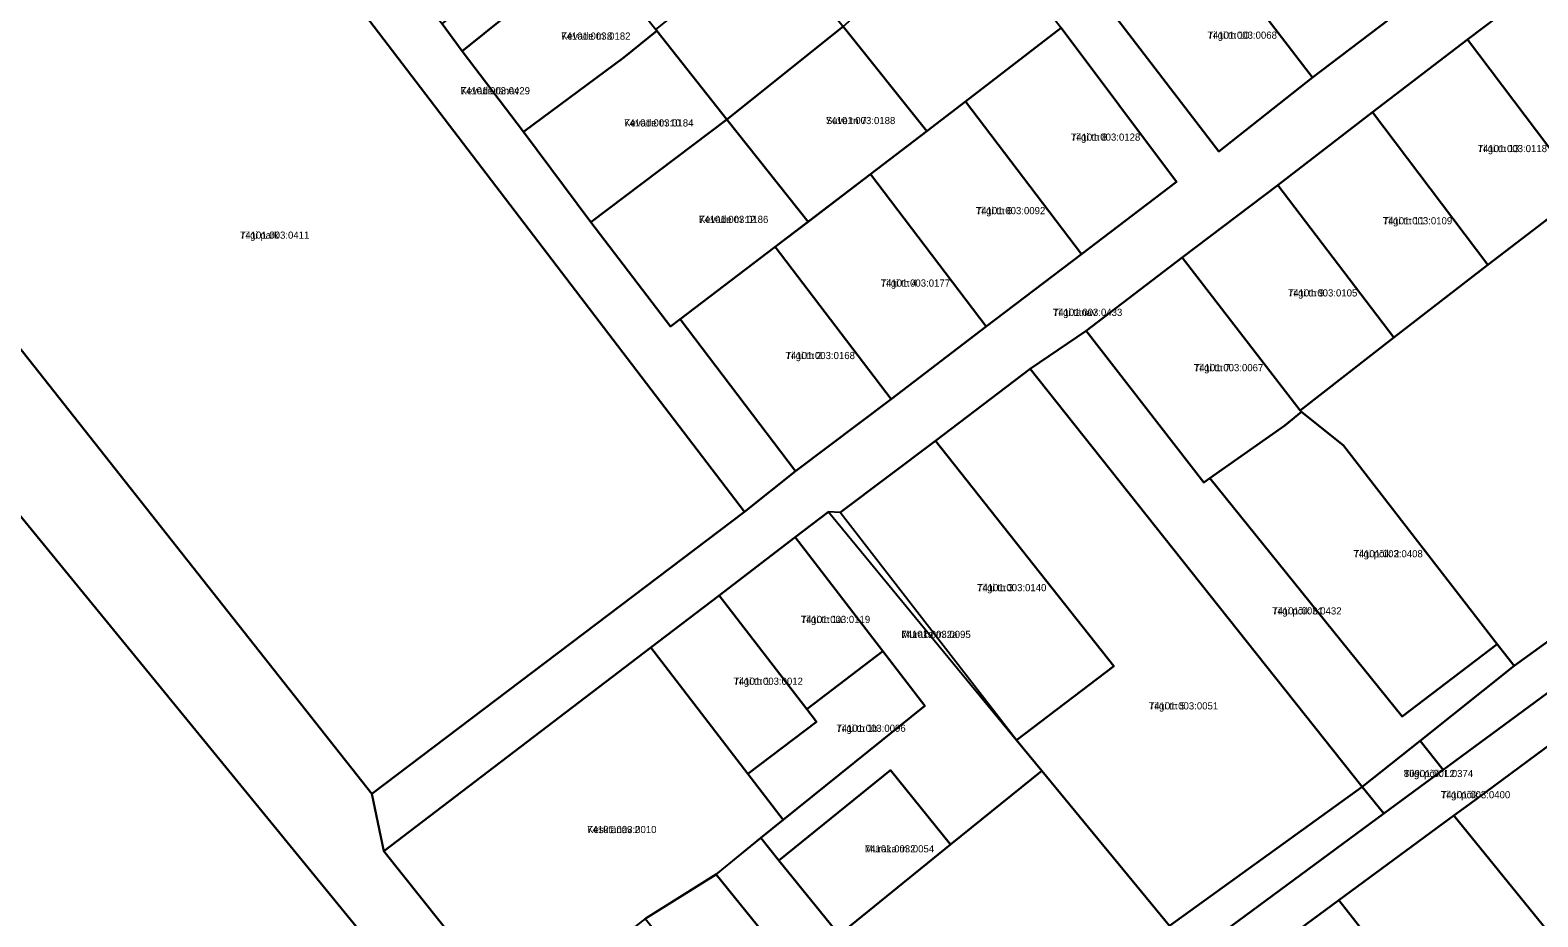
# Model space of a CAD drawing. Extents: x 524000 to 564260, y 6469338 to 6496391.
# Drawn here: x 538716.5 to 539031.7, y 6473655.1 to 6473840.4 of the extents above; entities that cross this region are included whole.
import ezdxf

# ---------------------------------------------------------------- set-up
doc = ezdxf.new("R2010")
doc.units = 0
for name, color, linetype in [('L_AADRESS', 7, 'Continuous'), ('PIIR', 7, 'Continuous'), ('TUNNUS', 7, 'Continuous')]:
    doc.layers.add(name, color=color, linetype=linetype)

msp = doc.modelspace()

# ---------------------------------------------------------------- linework, layer by layer
at = {"layer": 'PIIR'}
for points in [[(539001.2, 6473992.51), (538977.96, 6473973.83), (538953.19, 6473953.88), (538929.74, 6473935), (538905.62, 6473915.58), (538881.14, 6473895.86), (538857.67, 6473876.96), (538833.73, 6473857.7), (538806.82, 6473836.05), (538802.62, 6473841.76), (538829.42, 6473863.31), (538852.81, 6473882.12), (538877.13, 6473901.67), (538901.18, 6473920.98), (538925.27, 6473940.39), (538950.53, 6473960.69), (538973.46, 6473979.05), (538996.83, 6473997.86)], [(538746.69, 6473914.49), (538764.11, 6473892.45), (538777.15, 6473875.29), (538790.03, 6473858.33), (538802.62, 6473841.76), (538806.82, 6473836.05), (538819.61, 6473819.18), (538833.73, 6473800.28), (538850.34, 6473778.48), (538852.39, 6473780.04), (538876.52, 6473748.26), (538865.85, 6473739.73), (538736.45, 6473909.29)], [(538736.45, 6473909.29), (538865.85, 6473739.73), (538787.92, 6473680.82), (538654.87, 6473849.17)], [(538903.96, 6473819.33), (538886.44, 6473841.18), (538908.3, 6473860.63), (538934.93, 6473880.53), (538953.63, 6473857.22), (538945.95, 6473851.6), (538942.73, 6473855.45), (538928.99, 6473844.86), (538932.05, 6473840.9), (538912.03, 6473825.5)], [(538978.02, 6473875.71), (538980.21, 6473877.38), (539004.54, 6473845.63), (538984.63, 6473830.51), (538960.3, 6473862.25)], [(538960.3, 6473862.25), (538984.63, 6473830.51), (538964.98, 6473815.05), (538940.68, 6473846.82), (538945.95, 6473851.6), (538953.63, 6473857.22)], [(538847.31, 6473840.54), (538871.49, 6473859.78), (538886.44, 6473841.18), (538862.17, 6473821.77), (538847.5, 6473840.31)], [(538806.82, 6473836.05), (538833.73, 6473857.7), (538847.31, 6473840.54), (538847.5, 6473840.31), (538840.6, 6473834.68), (538819.61, 6473819.18)], [(539036.94, 6473853.58), (539061.24, 6473821.71), (539062.33, 6473820.29), (539053.46, 6473813.59), (539052.38, 6473815.03), (539041.12, 6473806.54), (539017.03, 6473838.47)], [(538819.61, 6473819.18), (538840.6, 6473834.68), (538847.5, 6473840.31), (538862.17, 6473821.77), (538833.73, 6473800.28)], [(538862.17, 6473821.77), (538886.44, 6473841.18), (538903.96, 6473819.33), (538892.17, 6473810.31), (538879.14, 6473800.39)], [(538912.03, 6473825.5), (538932.05, 6473840.9), (538956.15, 6473808.75), (538936.28, 6473793.58)], [(539061.24, 6473821.71), (539082.73, 6473838.08), (539088.7, 6473810.88), (539091.71, 6473754.61), (539026.77, 6473707.59), (539023.2, 6473712.09), (538991.08, 6473753.62), (538982.33, 6473760.65), (538982.02, 6473760.95), (539001.62, 6473776.19), (539021.24, 6473791.4), (539041.12, 6473806.54), (539052.38, 6473815.03), (539053.46, 6473813.59), (539062.33, 6473820.29)], [(539017.03, 6473838.47), (539041.12, 6473806.54), (539021.24, 6473791.4), (538997.15, 6473823.31)], [(538892.17, 6473810.31), (538903.96, 6473819.33), (538912.03, 6473825.5), (538936.28, 6473793.58), (538916.37, 6473778.46)], [(538833.73, 6473800.28), (538862.17, 6473821.77), (538879.14, 6473800.39), (538872.28, 6473795.17), (538852.39, 6473780.04), (538850.34, 6473778.48)], [(538997.15, 6473823.31), (539021.24, 6473791.4), (539001.62, 6473776.19), (538977.38, 6473808.01)], [(538892.17, 6473810.31), (538916.37, 6473778.46), (538896.48, 6473763.32), (538872.28, 6473795.17)], [(538977.38, 6473808.01), (539001.62, 6473776.19), (538982.02, 6473760.95), (538957.32, 6473792.91)], [(538872.28, 6473795.17), (538896.48, 6473763.32), (538876.52, 6473748.26), (538852.39, 6473780.04)], [(538937.29, 6473777.59), (538957.32, 6473792.91), (538982.02, 6473760.95), (538982.33, 6473760.65), (538978.84, 6473757.8), (538963.11, 6473746.78), (538961.91, 6473745.87)], [(538937.29, 6473777.59), (538961.91, 6473745.87), (538963.11, 6473746.78), (539003.32, 6473696.95), (539023.2, 6473712.09), (539026.77, 6473707.59), (539007.08, 6473691.91), (538995, 6473682.29), (538962.95, 6473722.6), (538925.56, 6473769.64)], [(538943.08, 6473707.51), (538905.75, 6473754.62), (538925.56, 6473769.64), (538962.95, 6473722.6), (538995, 6473682.29), (538954.69, 6473653.23), (538928, 6473685.61), (538922.7, 6473692.04)], [(538963.11, 6473746.78), (538978.84, 6473757.8), (538982.33, 6473760.65), (538991.08, 6473753.62), (539023.2, 6473712.09), (539003.32, 6473696.95)], [(538905.75, 6473754.62), (538943.08, 6473707.52), (538922.7, 6473692.04), (538885.84, 6473739.63)], [(539094.55, 6473746.64), (539056.85, 6473718.91), (539011.9, 6473685.81), (539007.08, 6473691.91), (539026.77, 6473707.59), (539091.71, 6473754.61)], [(538709.75, 6473744.57), (538805.02, 6473628.17), (538750.07, 6473585.88), (538725.42, 6473617.84), (538679.81, 6473582.76), (538647.18, 6473557.76), (538578.36, 6473641.86), (538617.86, 6473672.9), (538640.32, 6473688.84), (538662.71, 6473706.28), (538661.89, 6473707.3), (538663.52, 6473708.61), (538679.92, 6473721.87), (538696.31, 6473735.13), (538697.01, 6473734.27)], [(538873.95, 6473675.34), (538903.51, 6473699.2), (538894.73, 6473710.64), (538876.46, 6473734.44), (538883.39, 6473739.72), (538922.7, 6473692.04), (538928, 6473685.61), (538908.94, 6473670.21), (538896.36, 6473685.76), (538873.05, 6473666.9), (538869.28, 6473671.57)], [(538876.46, 6473734.44), (538894.73, 6473710.64), (538878.84, 6473698.51), (538860.51, 6473722.27)], [(538860.51, 6473722.27), (538878.84, 6473698.51), (538880.87, 6473695.87), (538866.56, 6473684.97), (538846.26, 6473711.4)], [(539056.85, 6473718.91), (539062.52, 6473711.91), (539038.34, 6473694.1), (539017.39, 6473678.66), (539014.17, 6473676.29), (539011.75, 6473674.51), (538990.07, 6473658.55), (538966.02, 6473640.83), (538960.39, 6473647.87), (538999.54, 6473676.7), (539011.9, 6473685.81)], [(538846.26, 6473711.4), (538866.56, 6473684.97), (538873.95, 6473675.34), (538869.28, 6473671.57), (538859.95, 6473664.03), (538845.12, 6473654.76), (538821.51, 6473636.25), (538818.36, 6473633.78), (538790.44, 6473668.85)], [(538880.87, 6473695.87), (538878.84, 6473698.51), (538894.73, 6473710.64), (538903.51, 6473699.2), (538873.95, 6473675.34), (538866.56, 6473684.97)], [(538999.54, 6473676.7), (538995, 6473682.29), (539007.08, 6473691.91), (539011.9, 6473685.81)], [(539038.34, 6473694.1), (539067.14, 6473658.54), (539045.45, 6473642.43), (539043.04, 6473640.64), (539014.17, 6473676.29), (539017.39, 6473678.66)], [(538873.05, 6473666.9), (538896.36, 6473685.76), (538908.94, 6473670.21), (538885.62, 6473651.35)], [(538908.94, 6473670.21), (538928, 6473685.61), (538954.69, 6473653.23), (538910.61, 6473620.45), (538885.62, 6473651.35)], [(538995, 6473682.29), (538999.54, 6473676.7), (538960.39, 6473647.87), (538939.32, 6473632.35), (538940.88, 6473630.4), (538917.47, 6473611.64), (538910.61, 6473620.45), (538954.69, 6473653.23)], [(539014.17, 6473676.29), (539043.04, 6473640.64), (539047.56, 6473635.06), (539045.15, 6473633.28), (539022.86, 6473616.87), (538990.07, 6473658.55), (539011.75, 6473674.51)], [(538859.92, 6473663.97), (538900.95, 6473613.21), (538886.74, 6473602.64), (538870.06, 6473623.44), (538857.57, 6473639.06), (538845.08, 6473654.7)], [(538990.07, 6473658.55), (539022.86, 6473616.87), (538999.14, 6473599.41), (538990.01, 6473610.82), (538966.02, 6473640.83)]]:
    msp.add_lwpolyline(points, close=True, dxfattribs=at)
for points in [[(538805.02, 6473628.17), (538709.75, 6473744.57), (538713.7, 6473747.76), (538676.56, 6473792.6), (538673.07, 6473796.98), (538660.77, 6473812.74), (538644.06, 6473833.57), (538633.76, 6473842.23), (538620.7, 6473881.22), (538614.61, 6473900.83), (538613.2, 6473905.36), (538604.14, 6473934.51), (538620, 6473945.96), (538620.45, 6473944.55), (538644.12, 6473912.24), (538667.75, 6473879.97), (538646.4, 6473864.34), (538654.87, 6473849.17), (538787.92, 6473680.82), (538790.44, 6473668.85), (538818.36, 6473633.78)], [(539036.94, 6473853.58), (539017.03, 6473838.47), (538997.15, 6473823.31), (538977.38, 6473808.01), (538957.32, 6473792.91), (538937.29, 6473777.59), (538925.56, 6473769.64), (538905.75, 6473754.62), (538885.84, 6473739.63), (538883.39, 6473739.72), (538876.46, 6473734.44), (538860.51, 6473722.27), (538846.26, 6473711.4), (538790.44, 6473668.85), (538787.92, 6473680.82), (538865.85, 6473739.73), (538876.52, 6473748.26), (538896.48, 6473763.32), (538916.37, 6473778.46), (538936.28, 6473793.58), (538956.15, 6473808.75), (538932.05, 6473840.9)], [(538940.68, 6473846.82), (538964.98, 6473815.05), (538984.63, 6473830.51), (539004.54, 6473845.63)], [(538900.95, 6473613.21), (538859.92, 6473663.97), (538869.28, 6473671.57), (538873.05, 6473666.9), (538885.62, 6473651.35)]]:
    msp.add_lwpolyline(points, dxfattribs=at)

# ---------------------------------------------------------------- texts
at = {"layer": 'L_AADRESS'}
for s, p in [('Kevade tn 8', (538827.5, 6473838.44)), ('Tiigi tn 10', (538962.66, 6473838.63)), ('Kevade tänav', (538806.49, 6473827.01)), ('Kevade tn 10', (538840.67, 6473820.29)), ('Suve tn 7', (538882.87, 6473820.79)), ('Tiigi tn 8', (538934.09, 6473817.32)), ('Tiigi tn 13', (539019.13, 6473814.93)), ('Tiigi tn 6', (538914.23, 6473801.95)), ('Kevade tn 12', (538856.32, 6473800.12)), ('Tiigi tn 11', (538999.31, 6473799.84)), ('Tiigi park', (538760.36, 6473796.83)), ('Tiigi tn 4', (538894.32, 6473786.82)), ('Tiigi tn 9', (538979.47, 6473784.76)), ('Tiigi tänav', (538930.33, 6473780.7)), ('Tiigi tn 2', (538874.43, 6473771.67)), ('Tiigi tn 7', (538959.81, 6473769.13)), ('Tiigi põik 2', (538993.16, 6473730.24)), ('Tiigi tn 3', (538914.46, 6473723.15)), ('Tiigi põik L1', (538976.17, 6473718.29)), ('Tiigi tn 1a', (538877.62, 6473716.51)), ('Muraka tn 2a', (538898.64, 6473713.38)), ('Tiigi tn 1', (538863.56, 6473703.59)), ('Tiigi tn 5', (538950.38, 6473698.44)), ('Tiigi tn 1b', (538885.04, 6473693.76)), ('Tiigi põik L2', (539003.69, 6473684.3)), ('Tiigi põik', (539011.44, 6473679.87)), ('Kesktänav 2', (538832.94, 6473672.59)), ('Muraka tn 2', (538890.99, 6473668.56))]:
    msp.add_text(s, height=1.5, dxfattribs=at).set_placement(p)
at = {"layer": 'TUNNUS'}
for s, p in [('74101:003:0182', (538827.5, 6473838.44)), ('74101:003:0068', (538962.66, 6473838.63)), ('74101:003:0429', (538806.49, 6473827.01)), ('74101:003:0184', (538840.67, 6473820.29)), ('74101:003:0188', (538882.87, 6473820.79)), ('74101:003:0128', (538934.09, 6473817.32)), ('74101:003:0118', (539019.13, 6473814.93)), ('74101:003:0092', (538914.23, 6473801.95)), ('74101:003:0186', (538856.32, 6473800.12)), ('74101:003:0109', (538999.31, 6473799.84)), ('74101:003:0411', (538760.36, 6473796.83)), ('74101:003:0177', (538894.32, 6473786.82)), ('74101:003:0105', (538979.47, 6473784.76)), ('74101:003:0433', (538930.33, 6473780.7)), ('74101:003:0168', (538874.43, 6473771.67)), ('74101:003:0067', (538959.81, 6473769.13)), ('74101:003:0408', (538993.16, 6473730.24)), ('74101:003:0140', (538914.46, 6473723.15)), ('74101:003:0432', (538976.17, 6473718.29)), ('74101:003:0119', (538877.62, 6473716.51)), ('74101:003:0095', (538898.64, 6473713.38)), ('74101:003:0012', (538863.56, 6473703.59)), ('74101:003:0051', (538950.38, 6473698.44)), ('74101:003:0096', (538885.04, 6473693.76)), ('80901:001:0374', (539003.69, 6473684.3)), ('74101:003:0400', (539011.44, 6473679.87)), ('74101:003:0010', (538832.94, 6473672.59)), ('74101:003:0054', (538890.99, 6473668.56))]:
    msp.add_text(s, height=1.5, dxfattribs=at).set_placement(p)

doc.saveas('drawing.dxf')
